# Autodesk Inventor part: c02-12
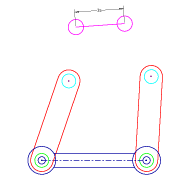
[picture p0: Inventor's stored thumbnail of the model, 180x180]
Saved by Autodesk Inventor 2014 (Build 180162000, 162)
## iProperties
Created: 2011-02
Part Number: c02-12
Material: Generic
Document SubType Name: Modeling
Designer: Thom Tremblay
Density: 1 g/cm^3
Appearance: Generic
Author: Thom Tremblay
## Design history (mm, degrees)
node "Blocks"
  sketch "Link 1"
    geometry: L1 (0, -8)-(60, -8); L2 (60, 8)-(0, 8); C1 r 5 at (0, 0); C2 r 5 at (60, 0); A1 r 8 centre (60, 0) between (60, -8) and (60, 8); A2 r 8 centre (0, 0) between (0, 8) and (0, -8); 1 further point
    constraints: 4 centre point, 4 end point, 4 point on circle, 4 tangent, 3 coincident, 1 equal radius, 1 horizontal, 1 parallel
    dimensions: "d0" = 60 distance of L1.start L1.end; "d1" = 10 diameter of C1; "d2" = 8 radius of A2
  sketch "Base"
    geometry: L1 (0, 0)-(75, 0); L2 (8.66, 5)-(66.34, 5); L3 (8.66, -5)-(66.34, -5); C1 r 2.654 at (0, 0); C2 r 2.654 at (75, 0); A1 r 10 centre (0, 0) between (8.66, 5) and (8.66, -5); A2 r 10 centre (75, 0) between (66.34, 5) and (66.34, -5); 1 further point
    constraints: 6 end point, 4 centre point, 4 point on circle, 3 parallel, 2 coincident, 2 equal radius, 1 horizontal
sketch "Linkage"
  geometry: L1 (24.396, 95.361)-(59.307, 97.851); C1 r 5.5 at (24.396, 95.361); C2 r 5.5 at (59.307, 97.851); 1 further point
  constraints: 2 centre point, 2 end point, 1 equal radius, 1 other
  dimensions: "d5" = 35 distance of L1.start L1.end
  node "Link 1:2"
  node "Link 1:3"
  node "Base:1"
